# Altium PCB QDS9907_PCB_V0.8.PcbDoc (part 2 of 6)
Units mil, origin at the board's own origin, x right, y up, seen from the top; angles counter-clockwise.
Board outline 3410.03 x 4010.03 mil, 8 copper layers (Top Layer, GND1, INT1, INT2, PWR1, GND2, GND3, Bottom Layer), stack 81.668 mil thick; 250 components, 129 nets, 7010 pads, 701 vias.
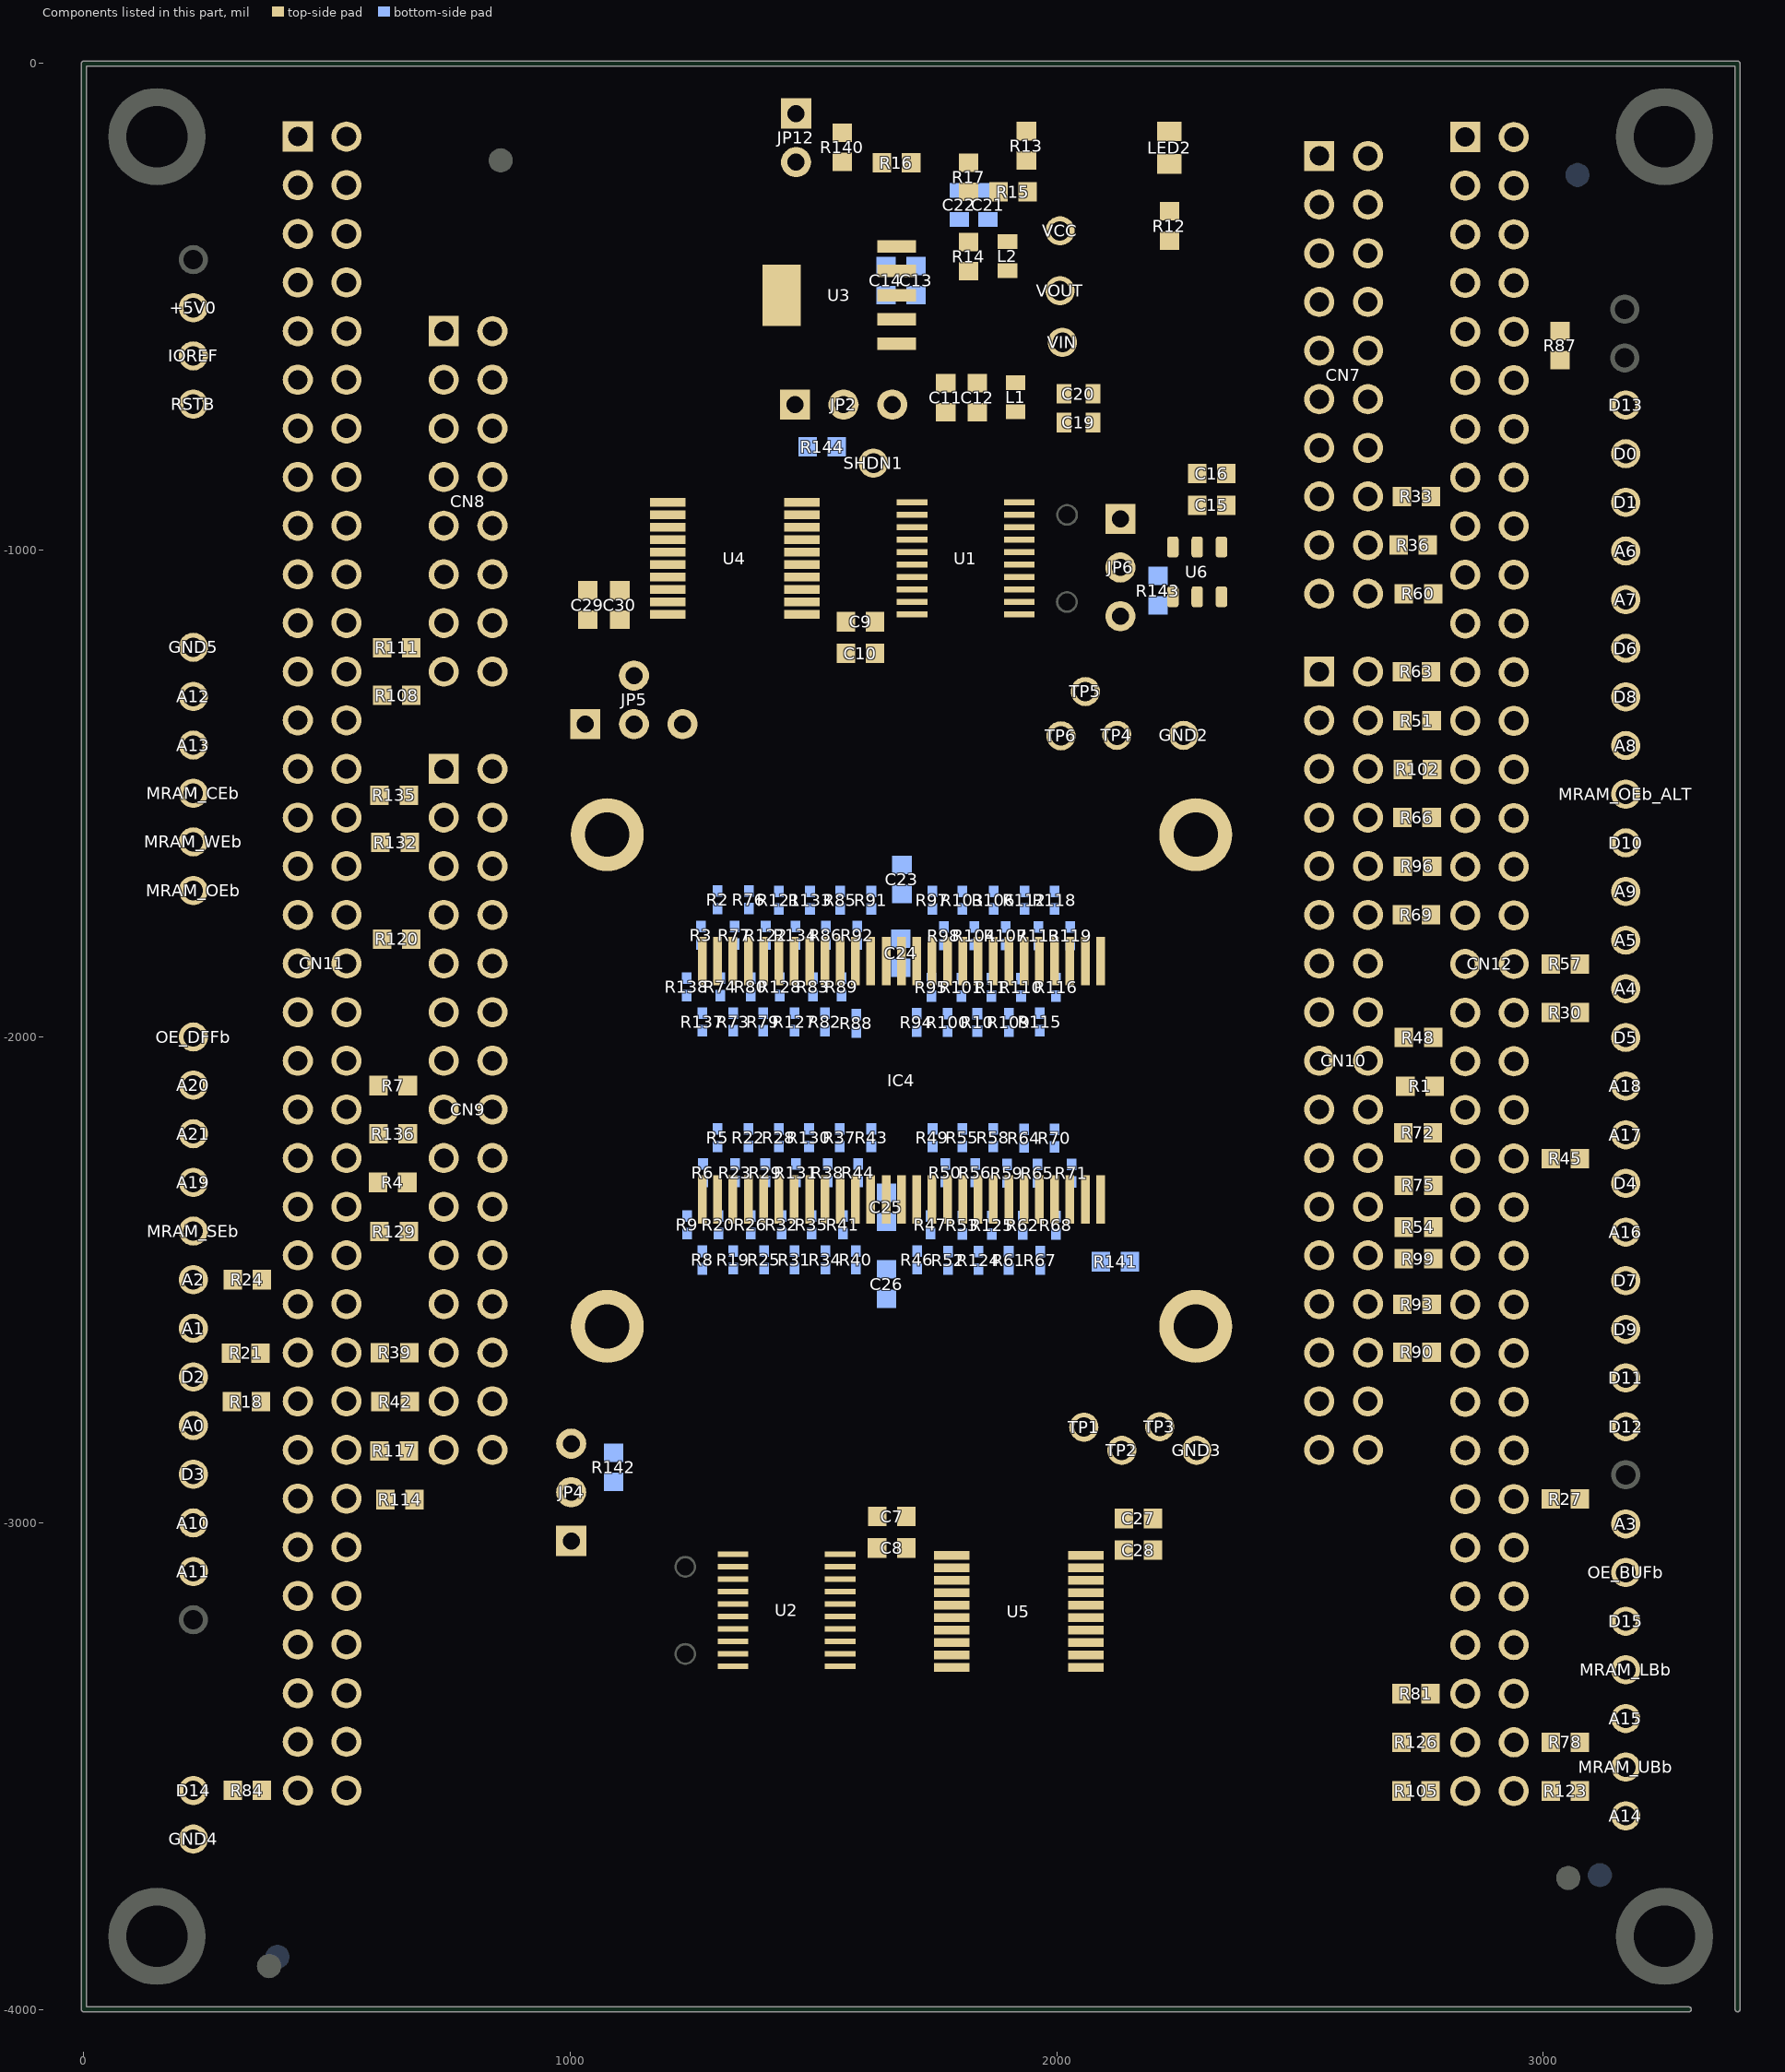
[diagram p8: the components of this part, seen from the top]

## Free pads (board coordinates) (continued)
  round 1.54 on Bottom Overlay: ""(1221.17,-3795.06) ""(1221.17,-3795.06) ""(1221.18,-3795.06) ""(1221.18,-3795.06) ""(1227.69,-3795.06) ""(1227.69,-3795.06) ""(1227.69,-3795.06) ""(1227.69,-3795.06) ""(1232.45,-3795.26) ""(1232.45,-3795.26) ""(1232.45,-3795.26) ""(1232.45,-3795.26) ""(1232.64,-3780.92) ""(1232.64,-3780.92) ""(1232.64,-3780.92) ""(1232.64,-3780.92) ""(1232.98,-3782.61) ""(1232.98,-3782.61) ""(1232.98,-3782.61) ""(1232.98,-3782.61) ""(1233.15,-3796.22) ""(1233.15,-3796.22) ""(1233.15,-3796.22) ""(1233.15,-3796.22) ""(1233.16,-3794.6) ""(1233.16,-3794.6) ""(1233.16,-3794.6) ""(1233.16,-3794.6) ""(1233.16,-3779.39) ""(1233.16,-3779.39) ""(1233.16,-3779.39) ""(1233.16,-3779.39) ""(1233.55,-3783.18) ""(1233.55,-3783.18) ""(1233.55,-3783.18) ""(1233.55,-3783.18) ""(1234.71,-3795.82) ""(1234.71,-3795.82) ""(1234.71,-3795.82) ""(1234.71,-3795.82) ""(1234.75,-3797.54) ""(1234.75,-3797.54) ""(1234.75,-3797.54) ""(1234.75,-3797.54) ""(1234.81,-3783.68) ""(1234.81,-3783.68) ""(1234.81,-3783.68) ""(1234.81,-3783.68) ""(1236.07,-3783.52) ""(1236.07,-3783.52) ""(1236.07,-3783.52) ""(1236.07,-3783.52) ""(1236.72,-3796.88) ""(1236.72,-3796.88) ""(1236.72,-3796.88) ""(1236.72,-3796.88) ""(1236.78,-3777.08) ""(1236.78,-3777.08) ""(1236.78,-3777.08) ""(1236.78,-3777.08) ""(1236.88,-3779.98) ""(1236.88,-3779.98) ""(1236.88,-3779.98) ""(1236.88,-3779.98) ""(1236.99,-3783.06) ""(1236.99,-3783.06) ""(1236.99,-3783.06) ""(1236.99,-3783.06) ""(1237.06,-3778.57) ""(1237.06,-3778.57) ""(1237.06,-3778.57) ""(1237.06,-3778.57) ""(1237.25,-3798.21) ""(1237.25,-3798.21) ""(1237.25,-3798.21) ""(1237.25,-3798.21) ""(1237.36,-3780.81) ""(1237.36,-3780.81) ""(1237.36,-3780.81) ""(1237.36,-3780.81) ""(1237.52,-3781.92) ""(1237.52,-3781.92) ""(1237.52,-3781.92) ""(1237.52,-3781.92) ""(1238.11,-3777.69) ""(1238.11,-3777.69) ""(1238.11,-3777.69) ""(1238.11,-3777.69) ""(1238.7,-3797) ""(1238.7,-3797) ""(1238.7,-3797) ""(1238.7,-3797) ""(1239.84,-3798.21) ""(1239.84,-3798.21) ""(1239.84,-3798.21) ""(1239.84,-3798.21) ""(1239.89,-3777.55) ""(1239.89,-3777.55) ""(1239.89,-3777.55) ""(1239.89,-3777.55) ""(1240.72,-3776.78) ""(1240.72,-3776.78) ""(1240.72,-3776.78) ""(1240.72,-3776.78) ""(1241.14,-3796.39) ""(1241.14,-3796.39) ""(1241.14,-3796.39) ""(1241.14,-3796.39) ""(1241.47,-3778.08) ""(1241.47,-3778.08) ""(1241.47,-3778.08) ""(1241.47,-3778.08) ""(1242.82,-3779.31) ""(1242.82,-3779.31) ""(1242.82,-3779.31) ""(1242.82,-3779.31) ""(1243.18,-3794.36) ""(1243.18,-3794.36) ""(1243.18,-3794.36) ""(1243.18,-3794.36) ""(1243.22,-3797.7) ""(1243.22,-3797.7) ""(1243.22,-3797.7) ""(1243.22,-3797.7) ""(1244.11,-3777.28) ""(1244.11,-3777.28) ""(1244.11,-3777.28) ""(1244.11,-3777.28) ""(1244.21,-3781.39) ""(1244.21,-3781.39) ""(1244.21,-3781.39) ""(1244.21,-3781.39) ""(1244.56,-3791.73) ""(1244.56,-3791.73) ""(1244.56,-3791.73) ""(1244.56,-3791.73) ""(1245.34,-3788.05) ""(1245.34,-3788.05) ""(1245.34,-3788.05) ""(1245.34,-3788.05) ""(1245.34,-3784.99) ""(1245.34,-3784.99) ""(1245.34,-3784.99) ""(1245.34,-3784.99) ""(1245.98,-3796.81) ""(1245.98,-3796.81) ""(1245.98,-3796.81) ""(1245.98,-3796.81) ""(1247.75,-3795.24) ""(1247.75,-3795.24) ""(1247.75,-3795.24) ""(1247.75,-3795.24) ""(1247.8,-3779.17) ""(1247.8,-3779.17) ""(1247.8,-3779.17) ""(1247.8,-3779.17) ""(1249.44,-3793.55) ""(1249.44,-3793.55) ""(1249.44,-3793.55) ""(1249.44,-3793.55) ""(1249.68,-3781.24) ""(1249.68,-3781.24) ""(1249.68,-3781.24) ""(1249.68,-3781.24) ""(1249.8,-3781.42) ""(1249.8,-3781.42) ""(1249.8,-3781.42) ""(1249.8,-3781.42) ""(1250.8,-3790.83) ""(1250.8,-3790.83) ""(1250.8,-3790.83) ""(1250.8,-3790.83) ""(1251.1,-3787.16) ""(1251.1,-3787.16) ""(1251.1,-3787.16) ""(1251.1,-3787.16) ""(1254.68,-3797.58) ""(1254.68,-3797.58) ""(1254.68,-3797.2) ""(1254.68,-3797.2) ""(1254.68,-3797.58) ""(1254.68,-3797.58) ""(1254.68,-3797.2) ""(1254.68,-3797.2) ""(1257.11,-3794.87) ""(1257.11,-3794.87) ""(1257.11,-3783.18) ""(1257.11,-3783.18) ""(1257.7,-3780.24) ""(1257.7,-3780.24) ""(1257.7,-3780.24) ""(1257.7,-3780.24) ""(1258.99,-3778.4) ""(1258.99,-3778.4) ""(1258.99,-3778.4) ""(1258.99,-3778.4) ""(1260.73,-3777.49) ""(1260.73,-3777.49) ""(1260.73,-3777.49) ""(1260.73,-3777.49) ""(1262.99,-3794.43) ""(1262.99,-3794.43) ""(1262.99,-3781.34) ""(1262.99,-3781.34) ""(1262.99,-3794.43) ""(1262.99,-3794.43) ""(1262.99,-3781.34) ""(1262.99,-3781.34) ""(1263.92,-3779.35) ""(1263.92,-3779.35) ""(1263.92,-3779.35) ""(1263.92,-3779.35) ""(1263.92,-3776.89) ""(1263.92,-3776.89) ""(1263.92,-3776.89) ""(1263.92,-3776.89) ""(1265.11,-3797.58) ""(1265.11,-3797.58) ""(1265.11,-3797.58) ""(1265.11,-3797.58) ""(1265.11,-3796.68) ""(1265.11,-3796.68) ""(1265.11,-3796.68) ""(1265.11,-3796.68) ""(1266,-3778.38) ""(1266,-3778.38) ""(1266,-3778.38) ""(1266,-3778.38) ""(1266.32,-3776.98) ""(1266.32,-3776.98) ""(1266.32,-3776.98) ""(1266.32,-3776.98) ""(1267.9,-3778.76) ""(1267.9,-3778.76) ""(1267.9,-3778.76) ""(1267.9,-3778.76) ""(1267.92,-3797.58) ""(1267.92,-3797.58) ""(1267.92,-3797.58) ""(1267.92,-3797.58) ""(1267.92,-3796.73) ""(1267.92,-3796.73) ""(1267.92,-3796.73) ""(1267.92,-3796.73) ""(1268.22,-3777.93) ""(1268.22,-3777.93) ""(1268.22,-3777.93) ""(1268.22,-3777.93) ""(1269.51,-3779.38) ""(1269.51,-3779.38) ""(1270.57,-3794.4) ""(1270.57,-3794.4) ""(1270.57,-3794.4) ""(1270.57,-3794.4) ""(1270.57,-3780.59) ""(1270.57,-3780.59) ""(1270.57,-3780.59) ""(1270.57,-3780.59) ""(1271.1,-3780.28) ""(1271.1,-3780.28) ""(1271.1,-3780.28) ""(1271.1,-3780.28) ""(1271.1,-3777.1) ""(1271.1,-3777.1) ""(1271.1,-3777.1) ""(1271.1,-3777.1) ""(1276.45,-3794.58) ""(1276.45,-3794.58) ""(1276.45,-3794.58) ""(1276.45,-3794.58) ""(1276.45,-3780.65) ""(1276.45,-3780.65) ""(1276.45,-3780.65) ""(1276.45,-3780.65) ""(1278.89,-3797.58) ""(1278.89,-3797.58) ""(1278.89,-3797.58) ""(1278.89,-3797.58) ""(1278.89,-3796.6) ""(1278.89,-3796.6) ""(1278.89,-3796.6) ""(1278.89,-3796.6) ""(1278.89,-3778.42) ""(1278.89,-3778.42) ""(1278.89,-3778.42) ""(1278.89,-3778.42) ""(1278.89,-3777.1) ""(1278.89,-3777.1) ""(1278.89,-3777.1) ""(1278.89,-3777.1) ""(1282.44,-3797.58) ""(1282.44,-3797.58) ""(1282.44,-3797) ""(1282.44,-3797) ""(1282.44,-3797.58) ""(1282.44,-3797.58) ""(1282.44,-3797) ""(1282.44,-3797) ""(1282.65,-3768.88) ""(1282.65,-3768.88) ""(1282.65,-3767.99) ""(1282.65,-3767.99) ""(1282.65,-3768.88) ""(1282.65,-3768.88) ""(1282.65,-3767.99) ""(1282.65,-3767.99) ""(1291.39,-3795.46) ""(1291.39,-3795.46) ""(1291.39,-3795.46) ""(1291.39,-3795.46) ""(1291.39,-3770.67) ""(1291.39,-3770.67) ""(1291.39,-3770.67) ""(1291.39,-3770.67) ""(1293.83,-3797.58) ""(1293.83,-3797.58) ""(1293.83,-3797.26) ""(1293.83,-3797.26) ""(1293.83,-3768.66) ""(1293.83,-3768.66) ""(1293.83,-3767.99) ""(1293.83,-3767.99) ""(1293.83,-3797.58) ""(1293.83,-3797.58) ""(1293.83,-3797.26) ""(1293.83,-3797.26) ""(1293.83,-3768.66) ""(1293.83,-3768.66) ""(1293.83,-3767.99) ""(1293.83,-3767.99) ""(1301.64,-3796.32) ""(1301.64,-3796.32) ""(1301.64,-3796.32) ""(1301.64,-3796.32) ""(1301.73,-3797.85) ""(1301.73,-3797.85) ""(1301.73,-3797.85) ""(1301.73,-3797.85) ""(1301.98,-3794.52) ""(1301.98,-3794.52) ""(1301.98,-3794.52) ""(1301.98,-3794.52) ""(1302.38,-3800.14) ""(1302.38,-3800.14) ""(1302.38,-3800.14) ""(1302.38,-3800.14) ""(1302.54,-3793.21) ""(1302.54,-3793.21) ""(1302.54,-3793.21) ""(1302.54,-3793.21) ""(1303.22,-3792.44) ""(1303.22,-3792.44) ""(1303.22,-3792.44) ""(1303.22,-3792.44) ""(1303.32,-3799.64) ""(1303.32,-3799.64) ""(1303.32,-3799.64) ""(1303.32,-3799.64) ""(1303.66,-3798.06) ""(1303.66,-3798.06) ""(1303.66,-3798.06) ""(1303.66,-3798.06) ""(1303.73,-3802.54) ""(1303.73,-3802.54) ""(1303.73,-3802.54) ""(1303.73,-3802.54) ""(1303.81,-3800.97) ""(1303.81,-3800.97) ""(1303.81,-3800.97) ""(1303.81,-3800.97) ""(1303.88,-3791.87) ""(1303.88,-3791.87) ""(1303.88,-3791.87) ""(1303.88,-3791.87) ""(1304.46,-3791.65) ""(1304.46,-3791.65) ""(1304.46,-3791.65) ""(1304.46,-3791.65) ""(1304.67,-3802.08) ""(1304.67,-3802.08) ""(1304.67,-3802.08) ""(1304.67,-3802.08) ""(1305.13,-3804.03) ""(1305.13,-3804.03) ""(1305.13,-3804.03) ""(1305.13,-3804.03) ""(1305.33,-3791.7) ""(1305.33,-3791.7) ""(1305.33,-3791.7) ""(1305.33,-3791.7) ""(1306.2,-3797.93) ""(1306.2,-3797.93) ""(1306.2,-3797.93) ""(1306.2,-3797.93) ""(1306.28,-3791.7) ""(1306.28,-3791.7) ""(1306.28,-3791.7) ""(1306.28,-3791.7) ""(1306.28,-3803.57) ""(1306.28,-3803.57) ""(1306.28,-3803.57) ""(1306.28,-3803.57) ""(1306.57,-3805.17) ""(1306.57,-3805.17) ""(1306.57,-3805.17) ""(1306.57,-3805.17) ""(1306.83,-3797.56) ""(1306.83,-3797.56) ""(1306.83,-3797.56) ""(1306.83,-3797.56) ""(1306.9,-3792.03) ""(1306.9,-3792.03) ""(1306.9,-3792.03) ""(1306.9,-3792.03) ""(1307.31,-3804.44) ""(1307.31,-3804.44) ""(1307.31,-3804.44) ""(1307.31,-3804.44) ""(1307.44,-3797.05) ""(1307.44,-3797.05) ""(1307.44,-3797.05) ""(1307.44,-3797.05) ""(1307.52,-3792.38) ""(1307.52,-3792.38) ""(1307.52,-3792.38) ""(1307.52,-3792.38) ""(1307.92,-3796.52) ""(1307.92,-3796.52) ""(1307.92,-3796.52) ""(1307.92,-3796.52) ""(1307.94,-3792.87) ""(1307.94,-3792.87) ""(1307.94,-3792.87) ""(1307.94,-3792.87) ""(1308.17,-3795.71) ""(1308.17,-3795.71) ""(1308.17,-3795.71) ""(1308.17,-3795.71) ""(1308.17,-3793.48) ""(1308.17,-3793.48) ""(1308.17,-3793.48) ""(1308.17,-3793.48) ""(1308.21,-3794.66) ""(1308.21,-3794.66) ""(1308.21,-3794.66) ""(1308.21,-3794.66) ""(1314.53,-3790.1) ""(1314.53,-3790.1) ""(1314.53,-3790.1) ""(1314.53,-3790.1) ""(1314.6,-3791.61) ""(1314.6,-3791.61) ""(1314.6,-3791.61) ""(1314.6,-3791.61) ""(1314.8,-3788.8) ""(1314.8,-3788.8) ""(1314.8,-3788.8) ""(1314.8,-3788.8) ""(1315.22,-3787.7) ""(1315.22,-3787.7) ""(1315.22,-3787.7) ""(1315.22,-3787.7) ""(1315.29,-3793.46) ""(1315.29,-3793.46) ""(1315.29,-3793.46) ""(1315.29,-3793.46) ""(1315.29,-3781.37) ""(1315.29,-3781.37) ""(1315.29,-3781.37) ""(1315.29,-3781.37) ""(1315.29,-3780.27) ""(1315.29,-3780.27) ""(1315.29,-3780.27) ""(1315.29,-3780.27) ""(1315.49,-3779.24) ""(1315.49,-3779.24) ""(1315.56,-3781.92) ""(1315.56,-3781.92) ""(1315.56,-3781.92) ""(1315.56,-3781.92) ""(1315.63,-3786.95) ""(1315.63,-3786.95) ""(1315.63,-3786.95) ""(1315.63,-3786.95) ""(1315.97,-3782.47) ""(1315.97,-3782.47) ""(1315.97,-3782.47) ""(1315.97,-3782.47) ""(1316.04,-3794.63) ""(1316.04,-3794.63) ""(1316.04,-3794.63) ""(1316.04,-3794.63) ""(1316.11,-3778.42) ""(1316.11,-3778.42) ""(1316.11,-3778.42) ""(1316.11,-3778.42) ""(1316.59,-3786.12) ""(1316.59,-3786.12) ""(1316.59,-3786.12) ""(1316.59,-3786.12) ""(1316.93,-3783.02) ""(1316.93,-3783.02) ""(1317,-3777.67) ""(1317,-3777.67) ""(1317.07,-3795.59) ""(1317.07,-3795.59) ""(1317.07,-3795.59) ""(1317.07,-3795.59) ""(1317.83,-3783.36) ""(1317.83,-3783.36) ""(1317.83,-3783.36) ""(1317.83,-3783.36) ""(1318.31,-3776.91) ""(1318.31,-3776.91) ""(1318.31,-3776.91) ""(1318.31,-3776.91) ""(1318.38,-3785.3) ""(1318.38,-3785.3) ""(1318.38,-3785.3) ""(1318.38,-3785.3) ""(1318.72,-3796.62) ""(1318.72,-3796.62) ""(1318.72,-3796.62) ""(1318.72,-3796.62) ""(1319.13,-3776.64) ""(1319.13,-3776.64) ""(1319.13,-3776.64) ""(1319.13,-3776.64) ""(1320.03,-3797.31) ""(1320.03,-3797.31) ""(1320.03,-3797.31) ""(1320.03,-3797.31) ""(1320.23,-3784.54) ""(1320.23,-3784.54) ""(1320.23,-3784.54) ""(1320.23,-3784.54) ""(1320.3,-3792.97) ""(1320.3,-3792.97) ""(1320.3,-3792.97) ""(1320.3,-3792.97) ""(1320.3,-3783.17) ""(1320.3,-3783.17) ""(1320.3,-3783.17) ""(1320.3,-3783.17) ""(1320.44,-3793.66) ""(1320.44,-3793.66) ""(1320.44,-3792.15) ""(1320.44,-3792.15) ""(1320.44,-3793.66) ""(1320.44,-3793.66) ""(1320.44,-3792.15) ""(1320.44,-3792.15) ""(1320.64,-3794.14) ""(1320.64,-3794.14) ""(1320.64,-3794.14) ""(1320.64,-3794.14) ""(1320.71,-3791.6) ""(1320.71,-3791.6) ""(1320.71,-3791.6) ""(1320.71,-3791.6) ""(1320.71,-3776.36) ""(1320.71,-3776.36) ""(1320.71,-3776.36) ""(1320.71,-3776.36) ""(1320.85,-3782.69) ""(1320.85,-3782.69) ""(1320.85,-3782.69) ""(1320.85,-3782.69) ""(1320.85,-3780.49) ""(1320.85,-3780.49) ""(1320.85,-3780.49) ""(1320.85,-3780.49) ""(1320.85,-3780.29) ""(1320.85,-3780.29) ""(1320.85,-3780.29) ""(1320.85,-3780.29) ""(1320.99,-3780.97) ""(1320.99,-3780.97) ""(1320.99,-3780.97) ""(1320.99,-3780.97) ""(1320.99,-3779.87) ""(1320.99,-3779.87) ""(1320.99,-3779.87) ""(1320.99,-3779.87) ""(1321.06,-3782.14) ""(1321.06,-3782.14) ""(1321.06,-3782.14) ""(1321.06,-3782.14) ""(1321.12,-3781.45) ""(1321.12,-3781.45) ""(1321.12,-3781.45) ""(1321.12,-3781.45) ""(1321.12,-3779.81) ""(1321.12,-3779.81) ""(1321.12,-3779.81) ""(1321.12,-3779.81) ""(1321.26,-3794.62) ""(1321.26,-3794.62) ""(1321.26,-3794.62) ""(1321.26,-3794.62) ""(1321.4,-3791.12) ""(1321.4,-3791.12) ""(1321.4,-3791.12) ""(1321.4,-3791.12) ""(1321.47,-3779.46) ""(1321.47,-3779.46) ""(1321.47,-3779.46) ""(1321.47,-3779.46) ""(1321.67,-3784.06) ""(1321.67,-3784.06) ""(1321.67,-3784.06) ""(1321.67,-3784.06) ""(1321.88,-3794.96) ""(1321.88,-3794.96) ""(1321.88,-3794.96) ""(1321.88,-3794.96) ""(1322.22,-3790.71) ""(1322.22,-3790.71) ""(1322.22,-3779.26) ""(1322.22,-3779.26) ""(1322.5,-3776.43) ""(1322.5,-3776.43) ""(1322.5,-3776.43) ""(1322.5,-3776.43) ""(1323.12,-3779.19) ""(1323.12,-3779.19) ""(1323.12,-3779.19) ""(1323.12,-3779.19) ""(1323.19,-3783.51) ""(1323.19,-3783.51) ""(1323.19,-3783.51) ""(1323.19,-3783.51) ""(1323.25,-3795.37) ""(1323.25,-3795.37) ""(1323.25,-3795.37) ""(1323.25,-3795.37) ""(1323.94,-3797.79) ""(1323.94,-3797.79) ""(1323.94,-3797.79) ""(1323.94,-3797.79) ""(1324.01,-3779.19) ""(1324.01,-3779.19) ""(1324.01,-3779.19) ""(1324.01,-3779.19) ""(1324.15,-3776.64) ""(1324.15,-3776.64) ""(1324.15,-3776.64) ""(1324.15,-3776.64) ""(1324.35,-3795.51) ""(1324.35,-3795.51) ""(1324.35,-3783.03) ""(1324.35,-3783.03) ""(1324.83,-3779.6) ""(1324.83,-3779.6) ""(1324.83,-3779.6) ""(1324.83,-3779.6) ""(1325.04,-3782.76) ""(1325.04,-3782.76) ""(1325.04,-3782.76) ""(1325.04,-3782.76) ""(1325.25,-3780.08) ""(1325.25,-3780.08) ""(1325.25,-3780.08) ""(1325.25,-3780.08) ""(1325.38,-3782.28) ""(1325.38,-3782.28) ""(1325.38,-3782.28) ""(1325.38,-3782.28) ""(1325.45,-3795.44) ""(1325.45,-3795.44) ""(1325.45,-3795.44) ""(1325.45,-3795.44) ""(1325.52,-3781.73) ""(1325.52,-3781.73) ""(1325.52,-3781.73) ""(1325.52,-3781.73) ""(1325.52,-3781.11) ""(1325.52,-3781.11) ""(1325.52,-3781.11) ""(1325.52,-3781.11) ""(1325.8,-3792.35) ""(1325.8,-3792.35) ""(1325.8,-3792.35) ""(1325.8,-3792.35) ""(1325.87,-3793.18) ""(1325.87,-3793.18) ""(1326,-3791.6) ""(1326,-3791.6) ""(1326,-3791.6) ""(1326,-3791.6) ""(1326.07,-3793.59) ""(1326.07,-3793.59) ""(1326.07,-3793.59) ""(1326.07,-3793.59) ""(1326.07,-3777.12) ""(1326.07,-3777.12) ""(1326.07,-3777.12) ""(1326.07,-3777.12) ""(1326.21,-3797.65) ""(1326.21,-3797.65) ""(1326.21,-3797.65) ""(1326.21,-3797.65) ""(1326.28,-3795.31) ""(1326.28,-3795.31) ""(1326.28,-3793.66) ""(1326.28,-3793.66) ""(1326.28,-3795.31) ""(1326.28,-3795.31) ""(1326.28,-3793.66) ""(1326.28,-3793.66) ""(1326.69,-3794.07) ""(1326.69,-3794.07) ""(1326.69,-3794.07) ""(1326.69,-3794.07) ""(1326.76,-3794.96) ""(1326.76,-3794.96) ""(1326.76,-3794.96) ""(1326.76,-3794.96) ""(1326.83,-3794.62) ""(1326.83,-3794.62) ""(1326.83,-3794.62) ""(1326.83,-3794.62) ""(1326.96,-3790.91) ""(1326.96,-3790.91) ""(1326.96,-3790.91) ""(1326.96,-3790.91) ""(1327.58,-3777.8) ""(1327.58,-3777.8) ""(1327.58,-3777.8) ""(1327.58,-3777.8) ""(1327.79,-3790.5) ""(1327.79,-3790.5) ""(1327.79,-3790.5) ""(1327.79,-3790.5) ""(1327.92,-3797.38) ""(1327.92,-3797.38) ""(1327.93,-3797.38) ""(1327.93,-3797.38) ""(1328.2,-3788.17) ""(1328.2,-3788.17) ""(1328.2,-3788.17) ""(1328.2,-3788.17) ""(1328.61,-3790.43) ""(1328.61,-3790.43) ""(1328.61,-3790.43) ""(1328.61,-3790.43) ""(1328.82,-3778.56) ""(1328.82,-3778.56) ""(1328.82,-3778.56) ""(1328.82,-3778.56) ""(1329.09,-3797.03) ""(1329.09,-3797.03) ""(1329.09,-3797.03) ""(1329.09,-3797.03) ""(1329.37,-3787.34) ""(1329.37,-3787.34) ""(1329.37,-3787.34) ""(1329.37,-3787.34) ""(1329.71,-3779.45) ""(1329.71,-3779.45) ""(1329.71,-3779.45) ""(1329.71,-3779.45) ""(1329.99,-3790.57) ""(1329.99,-3790.57) ""(1329.99,-3790.57) ""(1329.99,-3790.57) ""(1330.26,-3786.52) ""(1330.26,-3786.52) ""(1330.26,-3786.52) ""(1330.26,-3786.52) ""(1330.33,-3796.28) ""(1330.33,-3796.28) ""(1330.33,-3796.28) ""(1330.33,-3796.28) ""(1330.33,-3780.34) ""(1330.33,-3780.34) ""(1330.33,-3780.34) ""(1330.33,-3780.34) ""(1330.6,-3790.98) ""(1330.6,-3790.98) ""(1330.6,-3790.98) ""(1330.6,-3790.98) ""(1330.88,-3795.65) ""(1330.88,-3795.65) ""(1330.88,-3785.56) ""(1330.88,-3785.56) ""(1330.88,-3781.17) ""(1330.88,-3781.17) ""(1330.88,-3795.65) ""(1330.88,-3795.65) ""(1330.88,-3785.56) ""(1330.88,-3785.56) ""(1330.88,-3781.17) ""(1330.88,-3781.17) ""(1331.15,-3781.99) ""(1331.15,-3781.99) ""(1331.15,-3781.99) ""(1331.15,-3781.99) ""(1331.22,-3784.46) ""(1331.22,-3784.46) ""(1331.22,-3784.46) ""(1331.22,-3784.46) ""(1331.29,-3783.09) ""(1331.29,-3783.09) ""(1331.29,-3783.09) ""(1331.29,-3783.09) ""(1331.36,-3794.82) ""(1331.36,-3794.82) ""(1331.36,-3794.82) ""(1331.36,-3794.82) ""(1331.36,-3791.6) ""(1331.36,-3791.6) ""(1331.36,-3791.6) ""(1331.36,-3791.6) ""(1331.64,-3792.28) ""(1331.64,-3792.28) ""(1331.64,-3792.28) ""(1331.64,-3792.28) ""(1331.7,-3793.93) ""(1331.7,-3793.93) ""(1331.7,-3793.93) ""(1331.7,-3793.93) ""(1331.77,-3793.04) ""(1331.77,-3793.04) ""(1331.77,-3793.04) ""(1331.77,-3793.04) ""(1334.7,-3786.63) ""(1334.7,-3785.75) ""(1334.7,-3785.75) ""(1334.7,-3786.63) ""(1334.7,-3786.63) ""(1334.7,-3786.63) ""(1334.7,-3785.75) ""(1334.7,-3785.75) ""(1334.7,-3786.63) ""(1334.91,-3784.17) ""(1334.91,-3784.17) ""(1334.91,-3784.17) ""(1334.91,-3784.17) ""(1334.98,-3794.4) ""(1334.98,-3794.4) ""(1334.98,-3794.4) ""(1334.98,-3794.4) ""(1334.98,-3794.4) ""(1335.06,-3793.31) ""(1335.06,-3793.31) ""(1335.06,-3793.31) ""(1335.06,-3793.31) ""(1335.06,-3793.31) ""(1335.11,-3783.01) ""(1335.11,-3783.01) ""(1335.11,-3783.01) ""(1335.11,-3783.01) ""(1335.47,-3787.4) ""(1335.47,-3787.4) ""(1335.47,-3787.4) ""(1335.47,-3787.4) ""(1335.47,-3787.4) ""(1335.86,-3792.64) ""(1335.86,-3792.64) ""(1335.86,-3792.64) ""(1335.86,-3792.64) ""(1335.86,-3792.64) ""(1335.87,-3795.43) ""(1335.87,-3795.43) ""(1335.87,-3795.43) ""(1335.87,-3795.43) ""(1335.87,-3781.36) ""(1335.87,-3781.36) ""(1335.87,-3781.36) ""(1335.87,-3781.36) ""(1336.76,-3796.32) ""(1336.76,-3796.32) ""(1336.76,-3779.92) ""(1336.76,-3779.92) ""(1336.76,-3796.32) ""(1336.76,-3796.32) ""(1336.76,-3779.92) ""(1336.76,-3779.92) ""(1336.9,-3792.68) ""(1336.9,-3792.68) ""(1336.9,-3792.68) ""(1336.9,-3792.68) ""(1336.9,-3792.68) ""(1337.45,-3793.23) ""(1337.45,-3793.23) ""(1337.79,-3778.89) ""(1337.79,-3778.89) ""(1337.79,-3778.89) ""(1337.79,-3778.89) ""(1338.34,-3797.28) ""(1338.34,-3797.28) ""(1338.34,-3797.28) ""(1338.34,-3797.28) ""(1338.55,-3794.06) ""(1338.55,-3794.06) ""(1338.55,-3794.06) ""(1338.55,-3794.06) ""(1339.1,-3777.86) ""(1339.1,-3777.86) ""(1339.1,-3777.86) ""(1339.1,-3777.86) ""(1339.44,-3797.76) ""(1339.44,-3797.76) ""(1339.44,-3797.76) ""(1339.44,-3797.76) ""(1339.51,-3794.67) ""(1339.51,-3794.67) ""(1339.51,-3794.67) ""(1339.51,-3794.67) ""(1340.26,-3777.1) ""(1340.26,-3777.1) ""(1340.26,-3777.1) ""(1340.26,-3777.1) ""(1340.68,-3795.15) ""(1340.68,-3795.15) ""(1340.68,-3795.15) ""(1340.68,-3795.15) ""(1341.16,-3784.29) ""(1341.16,-3783.69) ""(1341.16,-3783.69) ""(1341.16,-3784.29) ""(1341.16,-3784.29) ""(1341.16,-3784.29) ""(1341.16,-3784.29) ""(1341.16,-3783.69) ""(1341.16,-3783.69) ""(1341.3,-3782.25) ""(1341.3,-3782.25) ""(1341.3,-3782.25) ""(1341.3,-3782.25) ""(1341.5,-3781.15) ""(1341.5,-3781.15) ""(1341.5,-3781.15) ""(1341.5,-3781.15) ""(1341.63,-3776.62) ""(1341.63,-3776.62) ""(1341.63,-3776.62) ""(1341.63,-3776.62) ""(1341.71,-3797.97) ""(1341.71,-3797.97) ""(1341.71,-3797.97) ""(1341.71,-3797.97) ""(1341.85,-3780.4) ""(1341.85,-3780.4) ""(1341.85,-3780.4) ""(1341.85,-3780.4) ""(1341.93,-3785.06) ""(1341.93,-3785.06) ""(1341.93,-3785.06) ""(1341.93,-3785.06) ""(1341.93,-3785.06) ""(1341.98,-3795.29) ""(1341.98,-3795.29) ""(1341.98,-3795.29) ""(1341.98,-3795.29) ""(1342.53,-3779.71) ""(1342.53,-3779.71) ""(1342.53,-3779.71) ""(1342.53,-3779.71) ""(1342.95,-3795.22) ""(1342.95,-3795.22) ""(1342.95,-3795.22) ""(1342.95,-3795.22) ""(1343.21,-3776.41) ""(1343.21,-3776.41) ""(1343.29,-3779.44) ""(1343.29,-3779.44) ""(1343.29,-3779.44) ""(1343.29,-3779.44) ""(1343.77,-3797.97) ""(1343.77,-3797.97) ""(1343.91,-3794.95) ""(1343.91,-3794.95) ""(1343.91,-3794.95) ""(1343.91,-3794.95) ""(1343.98,-3779.37) ""(1343.98,-3779.37) ""(1343.98,-3779.37) ""(1343.98,-3779.37) ""(1344.52,-3776.41) ""(1344.52,-3776.41) ""(1344.52,-3776.41) ""(1344.52,-3776.41) ""(1344.66,-3794.61) ""(1344.66,-3794.61) ""(1344.66,-3794.61) ""(1344.66,-3794.61) ""(1344.87,-3779.44) ""(1344.87,-3779.44) ""(1344.87,-3779.44) ""(1344.87,-3779.44) ""(1345.83,-3793.58) ""(1345.83,-3793.58) ""(1345.83,-3793.58) ""(1345.83,-3793.58) ""(1346.24,-3797.76) ""(1346.24,-3797.76) ""(1346.24,-3792.96) ""(1346.24,-3792.96) ""(1346.24,-3797.76) ""(1346.24,-3797.76) ""(1346.24,-3792.96) ""(1346.24,-3792.96) ""(1346.45,-3780.6) ""(1346.45,-3780.6) ""(1346.45,-3780.6) ""(1346.45,-3780.6) ""(1346.47,-3785.06) ""(1346.47,-3785.06) ""(1346.47,-3785.06) ""(1346.47,-3785.06) ""(1346.47,-3785.06) ""(1346.57,-3787.4) ""(1346.57,-3787.4) ""(1346.57,-3787.4) ""(1346.57,-3787.4) ""(1346.57,-3787.4) ""(1346.65,-3776.55) ""(1346.65,-3776.55) ""(1346.65,-3776.55) ""(1346.65,-3776.55) ""(1346.72,-3781.29) ""(1346.72,-3781.29) ""(1346.72,-3781.29) ""(1346.72,-3781.29) ""(1346.79,-3791.52) ""(1346.79,-3791.52) ""(1346.79,-3791.52) ""(1346.79,-3791.52) ""(1347,-3790.69) ""(1347,-3790.69) ""(1347,-3790.69) ""(1347,-3790.69) ""(1347.15,-3782.67) ""(1347.15,-3782.67) ""(1347.15,-3782.67) ""(1347.15,-3782.67) ""(1347.15,-3782.67) ""(1347.18,-3782.87) ""(1347.18,-3782.87) ""(1347.18,-3782.87) ""(1347.18,-3782.87) ""(1347.18,-3782.87) ""(1347.21,-3789.6) ""(1347.21,-3789.6) ""(1347.21,-3789.6) ""(1347.21,-3789.6) ""(1347.24,-3784.26) ""(1347.24,-3784.26) ""(1347.24,-3784.26) ""(1347.24,-3784.26) ""(1347.24,-3784.26) ""(1347.34,-3788.25) ""(1347.34,-3788.25) ""(1347.34,-3788.25) ""(1347.34,-3788.25) ""(1347.34,-3788.25) ""(1348.24,-3797.15) ""(1348.24,-3797.15) ""(1348.24,-3797.15) ""(1348.24,-3797.15) ""(1348.58,-3777.45) ""(1348.58,-3777.45) ""(1348.58,-3777.45) ""(1348.58,-3777.45) ""(1349.54,-3796.53) ""(1349.54,-3796.53) ""(1349.95,-3778.41) ""(1349.95,-3778.41) ""(1349.95,-3778.41) ""(1349.95,-3778.41) ""(1351.05,-3779.37) ""(1351.05,-3779.37) ""(1351.05,-3779.37) ""(1351.05,-3779.37) ""(1351.12,-3795.43) ""(1351.12,-3795.43) ""(1351.12,-3795.43) ""(1351.12,-3795.43) ""(1352.15,-3780.54) ""(1352.15,-3780.54) ""(1352.15,-3780.54) ""(1352.15,-3780.54) ""(1352.91,-3781.77) ""(1352.91,-3781.77) ""(1352.91,-3781.77) ""(1352.91,-3781.77) ""(1353.18,-3792.75) ""(1353.18,-3792.75) ""(1353.18,-3792.75) ""(1353.18,-3792.75) ""(1353.53,-3783.14) ""(1353.53,-3783.14) ""(1353.53,-3783.14) ""(1353.53,-3783.14) ""(1353.8,-3791.31) ""(1353.8,-3791.31) ""(1353.8,-3791.31) ""(1353.8,-3791.31) ""(1353.94,-3784.31) ""(1353.94,-3784.31) ""(1353.94,-3784.31) ""(1353.94,-3784.31) ""(1354.14,-3789.39) ""(1354.14,-3789.39) ""(1354.14,-3789.39) ""(1354.14,-3789.39) ""(1354.21,-3785.75) ""(1354.21,-3785.75) ""(1354.21,-3785.75) ""(1354.21,-3785.75) ""(1354.28,-3787.67) ""(1354.28,-3787.67) ""(1354.28,-3787.67) ""(1354.28,-3787.67) ""(1356.81,-3794.13) ""(1356.81,-3794.13) ""(1356.81,-3794.13) ""(1356.81,-3794.13) ""(1356.81,-3794.13) ""(1356.83,-3795.19) ""(1356.83,-3795.19) ""(1356.83,-3795.19) ""(1356.83,-3795.19) ""(1356.83,-3795.19) ""(1357.11,-3782.05) ""(1357.11,-3782.05) ""(1357.11,-3782.05) ""(1357.11,-3782.05) ""(1357.25,-3780.34) ""(1357.25,-3780.34) ""(1357.25,-3780.34) ""(1357.25,-3780.34) ""(1357.39,-3783.08) ""(1357.39,-3783.08) ""(1357.39,-3783.08) ""(1357.39,-3783.08) ""(1357.59,-3795.99) ""(1357.59,-3795.99) ""(1357.59,-3795.99) ""(1357.59,-3795.99) ""(1357.62,-3793.26) ""(1357.62,-3793.26) ""(1357.62,-3793.26) ""(1357.62,-3793.26) ""(1357.62,-3793.26) ""(1357.66,-3779.51) ""(1357.66,-3779.51) ""(1357.66,-3779.51) ""(1357.66,-3779.51) ""(1358.08,-3783.97) ""(1358.08,-3783.97) ""(1358.08,-3783.97) ""(1358.08,-3783.97) ""(1358.28,-3778.62) ""(1358.28,-3778.62) ""(1358.28,-3778.62) ""(1358.28,-3778.62) ""(1358.49,-3796.6) ""(1358.49,-3796.6) ""(1358.49,-3796.6) ""(1358.49,-3796.6) ""(1358.67,-3793.18) ""(1358.67,-3793.18) ""(1358.68,-3793.18) ""(1358.68,-3793.18) ""(1358.68,-3793.18) ""(1358.83,-3784.32) ""(1358.83,-3784.32) ""(1358.83,-3784.32) ""(1358.83,-3784.32) ""(1359.17,-3777.87) ""(1359.17,-3777.87) ""(1359.17,-3777.87) ""(1359.17,-3777.87) ""(1359.24,-3793.65) ""(1359.24,-3793.65) ""(1359.24,-3793.65) ""(1359.24,-3793.65) ""(1359.59,-3784.59) ""(1359.59,-3784.59) ""(1359.59,-3784.59) ""(1359.59,-3784.59) ""(1359.79,-3797.29) ""(1359.79,-3797.29) ""(1359.79,-3797.29) ""(1359.79,-3797.29) ""(1360,-3777.32) ""(1360,-3777.32) ""(1360,-3777.32) ""(1360,-3777.32) ""(1360.34,-3794.34) ""(1360.34,-3794.34) ""(1360.34,-3794.34) ""(1360.34,-3794.34) ""(1360.55,-3784.73) ""(1360.55,-3784.73) ""(1360.55,-3784.73) ""(1360.55,-3784.73) ""(1360.82,-3797.56) ""(1360.82,-3797.56) ""(1360.82,-3797.56) ""(1360.82,-3797.56) ""(1361.24,-3776.97) ""(1361.24,-3776.97) ""(1361.24,-3776.97) ""(1361.24,-3776.97) ""(1361.47,-3784.66) ""(1361.47,-3784.66) ""(1361.47,-3784.66) ""(1361.47,-3784.66) ""(1361.7,-3784.56) ""(1361.7,-3784.56) ""(1361.7,-3784.56) ""(1361.7,-3784.56) ""(1361.86,-3780.43) ""(1361.86,-3780.43) ""(1361.86,-3780.43) ""(1361.86,-3780.43) ""(1361.89,-3780.64) ""(1361.89,-3780.64) ""(1361.89,-3780.64) ""(1361.89,-3780.64) ""(1361.92,-3795.02) ""(1361.92,-3795.02) ""(1361.92,-3795.02) ""(1361.92,-3795.02) ""(1361.92,-3780.1) ""(1361.92,-3780.1) ""(1361.92,-3780.1) ""(1361.92,-3780.1) ""(1361.97,-3780.82) ""(1361.97,-3780.82) ""(1361.97,-3780.82) ""(1361.97,-3780.82) ""(1362.02,-3779.91) ""(1362.02,-3779.91) ""(1362.02,-3779.91) ""(1362.02,-3779.91) ""(1362.04,-3784.25) ""(1362.04,-3784.25) ""(1362.04,-3784.25) ""(1362.04,-3784.25) ""(1362.06,-3797.63) ""(1362.06,-3797.63) ""(1362.06,-3797.63) ""(1362.06,-3797.63) ""(1362.14,-3780.99) ""(1362.14,-3780.99) ""(1362.14,-3780.99) ""(1362.14,-3780.99) ""(1362.2,-3779.72) ""(1362.2,-3779.72) ""(1362.2,-3779.72) ""(1362.2,-3779.72) ""(1362.24,-3783.97) ""(1362.24,-3783.97) ""(1362.24,-3783.97) ""(1362.24,-3783.97) ""(1362.26,-3781.12) ""(1362.26,-3781.12) ""(1362.26,-3781.12) ""(1362.26,-3781.12) ""(1362.43,-3781.38) ""(1362.43,-3781.38) ""(1362.43,-3781.38) ""(1362.43,-3781.38) ""(1362.47,-3783.63) ""(1362.47,-3783.63) ""(1362.47,-3783.63) ""(1362.47,-3783.63) ""(1362.58,-3781.66) ""(1362.58,-3781.66) ""(1362.58,-3781.66) ""(1362.58,-3781.66) ""(1362.68,-3783.01) ""(1362.68,-3783.01) ""(1362.68,-3783.01) ""(1362.68,-3783.01) ""(1362.68,-3776.77) ""(1362.68,-3776.77) ""(1362.68,-3776.77) ""(1362.68,-3776.77) ""(1362.7,-3782.08) ""(1362.7,-3782.08) ""(1362.7,-3782.08) ""(1362.7,-3782.08) ""(1362.71,-3782.56) ""(1362.71,-3782.56) ""(1362.71,-3782.56) ""(1362.71,-3782.56) ""(1363.23,-3795.16) ""(1363.23,-3795.16) ""(1363.23,-3795.16) ""(1363.23,-3795.16) ""(1363.43,-3779.31) ""(1363.43,-3779.31) ""(1363.43,-3779.31) ""(1363.43,-3779.31) ""(1364.05,-3795.02) ""(1364.05,-3795.02) ""(1364.05,-3795.02) ""(1364.05,-3795.02) ""(1364.33,-3779.37) ""(1364.33,-3779.37) ""(1364.33,-3779.37) ""(1364.33,-3779.37) ""(1364.46,-3797.63) ""(1364.46,-3797.63) ""(1364.46,-3776.77) ""(1364.46,-3776.77) ""(1364.46,-3797.63) ""(1364.46,-3797.63) ""(1364.46,-3776.77) ""(1364.46,-3776.77) ""(1364.94,-3794.82) ""(1364.94,-3794.82) ""(1364.94,-3794.82) ""(1364.94,-3794.82) ""(1365.49,-3779.72) ""(1365.49,-3779.72) ""(1365.49,-3779.72) ""(1365.49,-3779.72) ""(1365.63,-3794.34) ""(1365.63,-3794.34) ""(1365.63,-3794.34) ""(1365.63,-3794.34) ""(1365.95,-3797.67) ""(1365.95,-3797.67) ""(1365.95,-3797.67) ""(1365.95,-3797.67) ""(1366.39,-3793.79) ""(1366.39,-3793.79) ""(1366.39,-3776.9) ""(1366.39,-3776.9) ""(1366.39,-3793.79) ""(1366.39,-3793.79) ""(1366.39,-3776.9) ""(1366.39,-3776.9) ""(1366.46,-3780.47) ""(1366.46,-3780.47) ""(1366.46,-3780.47) ""(1366.46,-3780.47) ""(1366.88,-3797.6) ""(1366.88,-3797.6) ""(1367.01,-3792.96) ""(1367.01,-3792.96) ""(1367.01,-3792.96) ""(1367.01,-3792.96) ""(1367.21,-3781.57) ""(1367.21,-3781.57) ""(1367.21,-3781.57) ""(1367.21,-3781.57) ""(1367.49,-3792) ""(1367.49,-3792) ""(1367.49,-3792) ""(1367.49,-3792) ""(1367.51,-3797.45) ""(1367.51,-3797.45) ""(1367.51,-3797.45) ""(1367.51,-3797.45) ""(1367.83,-3783.01) ""(1367.83,-3783.01) ""(1367.83,-3783.01) ""(1367.83,-3783.01) ""(1367.9,-3790.7) ""(1367.9,-3790.7) ""(1367.9,-3790.7) ""(1367.9,-3790.7) ""(1368.04,-3784.11) ""(1368.04,-3784.11) ""(1368.04,-3784.11) ""(1368.04,-3784.11) ""(1368.17,-3785.48) ""(1368.17,-3785.48) ""(1368.17,-3785.48) ""(1368.17,-3785.48) ""(1368.24,-3789.12) ""(1368.24,-3789.12) ""(1368.24,-3789.12) ""(1368.24,-3789.12) ""(1368.31,-3787.4) ""(1368.31,-3787.4) ""(1368.31,-3787.4) ""(1368.31,-3787.4) ""(1368.41,-3797.13) ""(1368.41,-3797.13) ""(1368.41,-3797.13) ""(1368.41,-3797.13) ""(1368.45,-3777.32) ""(1368.45,-3777.32) ""(1368.45,-3777.32) ""(1368.45,-3777.32) ""(1369.23,-3796.68) ""(1369.23,-3796.68) ""(1369.23,-3796.68) ""(1369.23,-3796.68) ""(1369.9,-3796.26) ""(1369.9,-3796.26) ""(1369.9,-3796.26) ""(1369.9,-3796.26) ""(1370.03,-3778.07) ""(1370.03,-3778.07) ""(1370.03,-3778.07) ""(1370.03,-3778.07) ""(1370.57,-3795.72) ""(1370.57,-3795.72) ""(1370.57,-3795.72) ""(1370.57,-3795.72) ""(1371.33,-3779.17) ""(1371.33,-3779.17) ""(1371.33,-3779.17) ""(1371.33,-3779.17) ""(1371.46,-3795.02) ""(1371.46,-3795.02) ""(1371.46,-3795.02) ""(1371.46,-3795.02) ""(1372.01,-3794.5) ""(1372.01,-3794.5) ""(1372.01,-3794.5) ""(1372.01,-3794.5) ""(1372.44,-3794.06) ""(1372.44,-3794.06) ""(1372.44,-3794.06) ""(1372.44,-3794.06) ""(1372.84,-3780.47) ""(1372.84,-3780.47) ""(1372.84,-3780.47) ""(1372.84,-3780.47) ""(1372.98,-3793.38) ""(1372.98,-3793.38) ""(1372.98,-3793.38) ""(1372.98,-3793.38) ""(1373.74,-3781.85) ""(1373.74,-3781.85) ""(1373.74,-3781.85) ""(1373.74,-3781.85) ""(1373.94,-3791.59) ""(1373.94,-3791.59) ""(1373.94,-3791.59) ""(1373.94,-3791.59) ""(1374.42,-3783.49) ""(1374.42,-3783.49) ""(1374.43,-3783.49) ""(1374.43,-3783.49) ""(1374.63,-3789.74) ""(1374.63,-3789.74) ""(1374.63,-3789.74) ""(1374.63,-3789.74) ""(1374.77,-3785) ""(1374.77,-3785) ""(1374.77,-3785) ""(1374.77,-3785) ""(1374.84,-3787.95) ""(1374.84,-3787.95) ""(1374.84,-3787.95) ""(1374.84,-3787.95) ""(1374.97,-3786.65) ""(1374.97,-3786.65) ""(1374.97,-3786.65) ""(1374.97,-3786.65) ""(1376.92,-3796.59) ""(1376.92,-3796.59) ""(1376.92,-3796.59) ""(1376.92,-3796.59) ""(1376.92,-3796.59) ""(1376.92,-3795.66) ""(1376.92,-3795.66) ""(1376.92,-3795.66) ""(1376.92,-3795.66) ""(1376.92,-3795.66) ""(1378.49,-3794.89) ""(1378.49,-3794.89) ""(1378.49,-3794.89) ""(1378.49,-3794.89) ""(1378.49,-3794.89) ""(1379.12,-3770.02) ""(1379.26,-3794.12) ""(1379.26,-3794.12) ""(1379.26,-3794.12) ""(1379.26,-3794.12) ""(1379.26,-3794.12) ""(1379.26,-3777.8) ""(1379.26,-3777.8) ""(1379.26,-3777.8) ""(1379.26,-3777.8) ""(1379.26,-3777.8) ""(1380.03,-3777.03) ""(1380.03,-3777.03) ""(1380.03,-3777.03) ""(1380.03,-3777.03) ""(1380.03,-3777.03) ""(1385.3,-3794.12) ""(1385.3,-3794.12) ""(1385.3,-3780.76) ""(1385.3,-3780.76) ""(1385.3,-3794.12) ""(1385.3,-3794.12) ""(1385.3,-3794.12) ""(1385.3,-3780.76) ""(1385.3,-3780.76) ""(1385.3,-3780.76) ""(1386.07,-3794.89) ""(1386.07,-3794.89) ""(1386.07,-3794.89) ""(1386.07,-3794.89) ""(1386.07,-3794.89) ""(1386.07,-3779.99) ""(1386.07,-3779.99) ""(1386.07,-3779.99) ""(1386.07,-3779.99) ""(1386.07,-3779.99) ""(1386.4,-3770.02) ""(1387.07,-3797.36) ""(1387.07,-3797.36) ""(1387.07,-3794.89) ""(1387.07,-3794.89) ""(1387.07,-3779.99) ""(1387.07,-3779.99) ""(1387.07,-3777.03) ""(1387.07,-3777.03) ""(1387.84,-3796.59) ""(1387.84,-3796.59) ""(1387.84,-3796.59) ""(1387.84,-3796.59) ""(1387.84,-3796.59) ""(1387.84,-3795.66) ""(1387.84,-3795.66) ""(1387.84,-3795.66) ""(1387.84,-3795.66) ""(1387.84,-3795.66) ""(1387.84,-3779.22) ""(1387.84,-3779.22) ""(1387.84,-3779.22) ""(1387.84,-3779.22) ""(1387.84,-3779.22) ""(1387.84,-3777.8) ""(1387.84,-3777.8) ""(1387.84,-3777.8) ""(1387.84,-3777.8) ""(1387.84,-3777.8) ""(1391.91,-3779.29) ""(1391.91,-3779.29) ""(1391.91,-3777.8) ""(1391.91,-3777.8) ""(1391.91,-3779.29) ""(1391.91,-3779.29) ""(1391.91,-3779.29) ""(1391.91,-3777.8) ""(1391.91,-3777.8) ""(1391.91,-3777.8) ""(1392.91,-3780.06) ""(1392.91,-3780.06) ""(1392.91,-3780.06) ""(1392.91,-3780.06) ""(1392.91,-3780.06) ""(1393.61,-3780.52) ""(1393.61,-3780.52) ""(1393.61,-3780.52) ""(1393.61,-3780.52) ""(1393.61,-3780.52) ""(1396.57,-3781.15) ""(1396.57,-3781.15) ""(1396.57,-3781.15) ""(1396.57,-3781.15) ""(1396.57,-3781.15) ""(1397.28,-3780.06) ""(1397.28,-3780.06) ""(1397.28,-3780.06) ""(1397.28,-3780.06) ""(1397.28,-3780.06) ""(1398.28,-3780.06) ""(1398.28,-3780.06) ""(1398.28,-3780.06) ""(1398.28,-3780.06) ""(1398.28,-3780.06) ""(1398.28,-3777.03) ""(1398.28,-3777.03) ""(1398.28,-3777.03) ""(1398.28,-3777.03) ""(1398.28,-3777.03) ""(1399.05,-3779.29) ""(1399.05,-3779.29) ""(1399.05,-3777.8) ""(1399.05,-3777.8) ""(1399.05,-3779.29) ""(1399.05,-3779.29) ""(1399.05,-3779.29) ""(1399.05,-3777.8) ""(1399.05,-3777.8) ""(1399.05,-3777.8) ""(1400.04,-3788.78) ""(1400.04,-3788.78) ""(1400.04,-3788.77) ""(1400.04,-3788.77) ""(1400.04,-3788.77) ""(1401.05,-3796.91) ""(1401.05,-3796.91) ""(1401.05,-3796.91) ""(1401.05,-3796.91) ""(1401.05,-3796.91) ""(1401.44,-3788.78) ""(1401.44,-3788.78) ""(1401.44,-3788.77) ""(1401.44,-3788.77) ""(1401.44,-3788.77) ""(1401.75,-3797.36) ""(1401.75,-3797.36) ""(1401.75,-3797.36) ""(1401.75,-3797.36) ""(1401.75,-3797.36) ""(1402.69,-3779.29) ""(1402.69,-3779.29) ""(1402.69,-3777.8) ""(1402.69,-3777.8) ""(1402.7,-3779.29) ""(1402.7,-3779.29) ""(1402.7,-3779.29) ""(1402.7,-3777.8) ""(1402.7,-3777.8) ""(1402.7,-3777.8) ""(1403.47,-3780.06) ""(1403.47,-3780.06) ""(1403.47,-3780.06) ""(1403.47,-3780.06) ""(1403.47,-3780.06) ""(1403.47,-3777.03) ""(1403.47,-3777.03) ""(1403.47,-3777.03) ""(1403.47,-3777.03) ""(1403.47,-3777.03) ""(1403.64,-3797.36) ""(1403.64,-3797.36) ""(1403.64,-3797.36) ""(1403.64,-3797.36) ""(1403.64,-3797.36) ""(1404.2,-3780.06) ""(1404.2,-3780.06) ""(1404.2,-3780.06) ""(1404.2,-3780.06) ""(1404.2,-3780.06) ""(1404.34,-3796.91) ""(1404.34,-3796.91) ""(1404.34,-3796.91) ""(1404.34,-3796.91) ""(1404.34,-3796.91) ""(1404.9,-3781.15) ""(1404.9,-3781.15) ""(1404.9,-3781.15) ""(1404.9,-3781.15) ""(1411.78,-3780.52) ""(1411.78,-3780.52) ""(1411.78,-3780.52) ""(1411.78,-3780.52) ""(1411.78,-3780.52) ""(1412.48,-3780.06) ""(1413.12,-3780.06) ""(1413.12,-3780.06) ""(1413.12,-3780.06) ""(1413.12,-3780.06) ""(1413.12,-3780.06) ""(1413.12,-3777.03) ""(1413.12,-3777.03) ""(1413.12,-3777.03) ""(1413.12,-3777.03) ""(1413.12,-3777.03) ""(1413.89,-3779.29) ""(1413.89,-3779.29) ""(1413.89,-3779.29) ""(1413.89,-3779.29) ""(1413.89,-3779.29) ""(1413.89,-3777.8) ""(1413.89,-3777.8) ""(1413.89,-3777.8) ""(1413.89,-3777.8) ""(1413.89,-3777.8) ""(1417.74,-3780.91) ""(1417.74,-3780.91) ""(1417.74,-3780.91) ""(1417.74,-3780.91) ""(1417.74,-3779.17) ""(1417.74,-3779.17) ""(1417.74,-3779.17) ""(1417.74,-3779.17) ""(1418,-3781.91) ""(1418,-3781.91) ""(1418,-3781.91) ""(1418,-3781.91) ""(1418.14,-3778.1) ""(1418.14,-3778.1) ""(1418.14,-3778.1) ""(1418.14,-3778.1) ""(1418.47,-3782.72) ""(1418.47,-3782.72) ""(1418.47,-3782.72) ""(1418.47,-3782.72) ""(1418.61,-3777.37) ""(1418.61,-3777.37) ""(1418.61,-3777.37) ""(1418.61,-3777.37) ""(1419.34,-3783.38) ""(1419.34,-3783.38) ""(1419.34,-3783.38) ""(1419.34,-3783.38) ""(1419.41,-3776.96) ""(1419.41,-3776.96) ""(1419.41,-3776.96) ""(1419.41,-3776.96) ""(1420.21,-3783.65) ""(1420.21,-3783.65) ""(1420.21,-3783.65) ""(1420.21,-3783.65) ""(1420.35,-3776.76) ""(1420.35,-3776.76) ""(1420.35,-3776.76) ""(1420.35,-3776.76) ""(1421.22,-3783.58) ""(1421.22,-3783.58) ""(1421.22,-3783.58) ""(1421.22,-3783.58) ""(1421.42,-3776.76) ""(1421.42,-3776.76) ""(1421.42,-3776.76) ""(1421.42,-3776.76) ""(1421.69,-3783.38) ""(1421.69,-3783.38) ""(1421.69,-3783.38) ""(1421.69,-3783.38) ""(1422.29,-3782.92) ""(1422.29,-3782.92) ""(1422.29,-3782.92) ""(1422.29,-3782.92) ""(1422.62,-3782.45) ""(1422.62,-3782.45) ""(1422.62,-3782.45) ""(1422.62,-3782.45) ""(1422.69,-3777.03) ""(1422.69,-3777.03) ""(1422.69,-3777.03) ""(1422.69,-3777.03) ""(1423.02,-3782.11) ""(1423.02,-3782.11) ""(1423.02,-3782.11) ""(1423.02,-3782.11) ""(1423.29,-3782.05) ""(1423.29,-3782.05) ""(1423.29,-3782.05) ""(1423.29,-3782.05) ""(1423.56,-3777.5) ""(1423.56,-3777.5) ""(1423.56,-3777.5) ""(1423.56,-3777.5) ""(1424.03,-3782.11) ""(1424.03,-3782.11) ""(1424.03,-3782.11) ""(1424.03,-3782.11) ""(1424.23,-3796.59) ""(1424.23,-3796.59) ""(1424.23,-3796.59) ""(1424.23,-3795.47) ""(1424.23,-3795.47) ""(1424.23,-3795.47) ""(1424.23,-3778.1) ""(1424.23,-3778.1) ""(1424.23,-3778.1) ""(1424.23,-3778.1) ""(1424.23,-3796.59) ""(1424.23,-3796.59) ""(1424.23,-3795.47) ""(1424.23,-3795.47) ""(1424.5,-3782.51) ""(1424.5,-3782.51) ""(1424.5,-3782.51) ""(1424.5,-3782.51) ""(1424.83,-3794.72) ""(1424.83,-3794.72) ""(1424.83,-3794.72) ""(1424.83,-3794.71) ""(1424.83,-3794.71) ""(1424.96,-3783.12) ""(1424.96,-3783.12) ""(1424.96,-3783.12) ""(1424.96,-3783.12) ""(1425,-3797.36) ""(1425,-3797.36) ""(1425,-3797.36) ""(1425,-3797.36) ""(1425,-3797.36) ""(1425.43,-3783.92) ""(1425.43,-3783.92) ""(1425.43,-3783.92) ""(1425.43,-3783.92) ""(1425.83,-3784.79) ""(1425.83,-3784.79) ""(1425.83,-3784.79) ""(1425.83,-3784.79) ""(1426.1,-3785.86) ""(1426.1,-3785.86) ""(1426.1,-3785.86) ""(1426.1,-3785.86) ""(1426.3,-3786.59) ""(1426.3,-3786.59) ""(1426.3,-3786.59) ""(1426.3,-3786.59) ""(1426.37,-3794.37) ""(1426.37,-3794.37) ""(1426.37,-3794.37) ""(1426.37,-3794.37) ""(1426.37,-3794.37) ""(1426.64,-3787.66) ""(1426.64,-3787.66) ""(1426.64,-3787.66) ""(1426.64,-3787.66) ""(1426.75,-3787.97) ""(1426.75,-3787.97) ""(1426.75,-3787.97) ""(1426.75,-3787.97) ""(1426.75,-3787.97) ""(1427.17,-3783.39) ""(1427.17,-3783.39) ""(1427.17,-3777.8) ""(1427.17,-3783.39) ""(1427.17,-3783.39) ""(1427.17,-3777.8) ""(1427.17,-3777.8) ""(1427.17,-3777.8) ""(1427.17,-3777.8) ""(1427.94,-3777.03) ""(1427.94,-3777.03) ""(1427.94,-3777.03) ""(1427.94,-3777.03) ""(1427.94,-3777.03) ""(1433.2,-3780.51) ""(1433.2,-3780.51) ""(1433.4,-3780.17) ""(1433.4,-3780.17) ""(1433.4,-3780.17) ""(1433.4,-3780.17) ""(1433.6,-3794.42) ""(1433.6,-3794.42) ""(1433.6,-3794.42) ""(1433.6,-3794.42) ""(1433.6,-3794.42) ""(1434.13,-3779.77) ""(1434.13,-3779.77) ""(1434.13,-3779.77) ""(1434.13,-3779.77) ""(1434.76,-3777.03) ""(1434.76,-3777.03) ""(1434.76,-3777.03) ""(1434.76,-3777.03) ""(1434.76,-3777.03) ""(1434.77,-3797.36) ""(1434.77,-3797.36) ""(1434.77,-3797.36) ""(1434.77,-3797.36) ""(1434.77,-3797.36) ""(1434.83,-3779.71) ""(1434.83,-3779.71) ""(1434.83,-3779.71) ""(1434.83,-3779.71) ""(1434.83,-3779.71) ""(1434.94,-3794.72) ""(1434.94,-3794.71) ""(1434.94,-3794.71) ""(1434.94,-3794.71) ""(1434.94,-3794.72) ""(1435.53,-3778.95) ""(1435.53,-3778.95) ""(1435.53,-3778.95) ""(1435.53,-3778.95) ""(1435.53,-3778.95) ""(1435.53,-3777.8) ""(1435.53,-3777.8) ""(1435.53,-3777.8) ""(1435.53,-3777.8) ""(1435.53,-3777.8) ""(1435.54,-3796.59) ""(1435.54,-3796.59) ""(1435.54,-3796.59) ""(1435.54,-3796.59) ""(1435.54,-3796.59) ""(1435.54,-3795.47) ""(1435.54,-3795.47) ""(1435.54,-3795.47) ""(1435.54,-3795.47) ""(1435.54,-3795.47) ""(1439.28,-3793.38) ""(1439.28,-3793.38) ""(1439.32,-3794.59) ""(1439.32,-3794.59) ""(1439.32,-3794.59) ""(1439.32,-3794.59) ""(1439.32,-3794.59) ""(1439.41,-3786.56) ""(1439.41,-3786.56) ""(1439.41,-3786.56) ""(1439.41,-3786.56) ""(1439.41,-3786.56) ""(1439.41,-3785.3) ""(1439.41,-3785.3) ""(1439.41,-3785.3) ""(1439.41,-3785.3) ""(1439.55,-3784.51) ""(1439.55,-3784.51) ""(1439.55,-3784.51) ""(1439.55,-3784.51) ""(1439.8,-3783.73) ""(1439.8,-3783.73) ""(1439.8,-3783.73) ""(1439.8,-3783.73) ""(1439.82,-3794.96) ""(1439.82,-3794.96) ""(1439.82,-3794.96) ""(1439.82,-3794.96) ""(1440.09,-3782.72) ""(1440.09,-3782.72) ""(1440.09,-3782.72) ""(1440.09,-3782.72) ""(1440.18,-3787.33) ""(1440.18,-3787.33) ""(1440.23,-3792.53) ""(1440.23,-3792.53) ""(1440.76,-3780.98) ""(1440.76,-3780.98) ""(1440.76,-3780.98) ""(1440.76,-3780.98) ""(1441.23,-3795.96) ""(1441.23,-3795.96) ""(1441.23,-3795.96) ""(1441.23,-3795.96) ""(1441.31,-3792.57) ""(1441.31,-3792.57) ""(1441.31,-3792.57) ""(1441.31,-3792.57) ""(1441.31,-3792.57) ""(1441.76,-3779.51) ""(1441.76,-3779.51) ""(1441.76,-3779.51) ""(1441.76,-3779.51) ""(1442.3,-3793.62) ""(1442.3,-3793.62) ""(1442.3,-3793.62) ""(1442.3,-3793.62) ""(1442.56,-3796.7) ""(1442.56,-3796.7) ""(1442.56,-3796.7) ""(1442.56,-3796.7) ""(1443.37,-3778.11) ""(1443.37,-3778.11) ""(1443.37,-3778.11) ""(1443.37,-3778.11) ""(1443.5,-3794.49) ""(1443.5,-3794.49) ""(1443.5,-3794.49) ""(1443.5,-3794.49) ""(1444.04,-3797.3) ""(1444.04,-3797.3) ""(1444.04,-3797.3) ""(1444.04,-3797.3) ""(1444.51,-3794.89) ""(1444.51,-3794.89) ""(1444.51,-3794.89) ""(1444.51,-3794.89) ""(1444.57,-3777.3) ""(1444.57,-3777.3) ""(1444.57,-3777.3) ""(1444.57,-3777.3) ""(1445.37,-3797.63) ""(1445.37,-3797.63) ""(1445.38,-3797.63) ""(1445.38,-3797.63) ""(1445.58,-3794.96) ""(1445.58,-3794.96) ""(1445.58,-3784.29) ""(1445.58,-3782.72) ""(1445.58,-3782.72) ""(1445.58,-3794.96) ""(1445.58,-3794.96) ""(1445.58,-3784.29) ""(1445.58,-3784.29) ""(1445.58,-3784.29) ""(1445.58,-3784.29) ""(1445.58,-3782.72) ""(1445.58,-3782.72) ""(1445.91,-3781.38) ""(1445.91,-3781.38) ""(1445.91,-3781.38) ""(1445.91,-3781.38) ""(1446.18,-3776.77) ""(1446.18,-3776.77) ""(1446.18,-3776.77) ""(1446.18,-3776.77) ""(1446.31,-3780.51) ""(1446.31,-3780.51) ""(1446.31,-3780.51) ""(1446.31,-3780.51) ""(1446.35,-3785.06) ""(1446.35,-3785.06) ""(1446.35,-3785.06) ""(1446.35,-3785.06) ""(1446.35,-3785.06) ""(1446.98,-3779.98) ""(1446.98,-3779.98) ""(1446.98,-3779.98) ""(1446.98,-3779.98) ""(1447.65,-3794.89) ""(1447.65,-3794.89) ""(1447.65,-3779.64) ""(1447.65,-3779.64) ""(1447.65,-3794.89) ""(1447.65,-3794.89) ""(1447.65,-3779.64) ""(1447.65,-3779.64) ""(1447.72,-3797.7) ""(1447.72,-3797.7) ""(1447.72,-3797.7) ""(1447.72,-3797.7) ""(1448.12,-3776.63) ""(1448.12,-3776.63) ""(1448.12,-3776.63) ""(1448.12,-3776.63) ""(1448.39,-3779.58) ""(1448.39,-3779.58) ""(1448.39,-3779.58) ""(1448.39,-3779.58) ""(1449.06,-3794.29) ""(1449.06,-3794.29) ""(1449.06,-3794.29) ""(1449.06,-3794.29) ""(1449.32,-3779.64) ""(1449.32,-3779.64) ""(1449.32,-3779.64) ""(1449.32,-3779.64) ""(1449.59,-3797.7) ""(1449.59,-3797.7) ""(1449.59,-3797.7) ""(1449.59,-3797.7) ""(1449.73,-3779.84) ""(1449.73,-3779.84) ""(1449.73,-3779.84) ""(1449.73,-3779.84) ""(1450.19,-3776.7) ""(1450.19,-3776.7) ""(1450.19,-3776.7) ""(1450.19,-3776.7) ""(1450.4,-3780.18) ""(1450.4,-3780.18) ""(1450.4,-3780.18) ""(1450.4,-3780.18) ""(1450.8,-3797.57) ""(1450.8,-3797.57) ""(1450.8,-3797.57) ""(1450.8,-3797.57) ""(1451,-3780.71) ""(1451,-3780.71) ""(1451,-3780.71) ""(1451,-3780.71) ""(1451.29,-3785.06) ""(1451.29,-3785.06) ""(1451.29,-3785.06) ""(1451.29,-3785.06) ""(1451.29,-3785.06) ""(1451.33,-3781.25) ""(1451.33,-3781.25) ""(1451.33,-3781.25) ""(1451.33,-3781.25) ""(1451.37,-3787.33) ""(1451.37,-3787.33) ""(1451.37,-3787.33) ""(1451.37,-3787.33) ""(1451.37,-3787.33) ""(1451.53,-3781.77) ""(1451.53,-3781.77) ""(1451.53,-3781.77) ""(1451.53,-3781.77) ""(1451.67,-3791.21) ""(1451.67,-3791.21) ""(1451.67,-3791.21) ""(1451.67,-3791.21) ""(1451.72,-3782.31) ""(1451.72,-3782.31) ""(1451.72,-3782.31) ""(1451.72,-3782.31) ""(1451.89,-3782.89) ""(1451.89,-3782.89) ""(1451.89,-3782.89) ""(1451.89,-3782.89) ""(1451.93,-3777.17) ""(1451.93,-3777.17) ""(1451.93,-3777.17) ""(1451.93,-3777.17) ""(1452,-3790.14) ""(1452,-3790.14) ""(1452,-3790.14) ""(1452,-3790.14) ""(1452.07,-3784.29) ""(1452.07,-3784.29) ""(1452.07,-3784.29) ""(1452.07,-3784.29) ""(1452.07,-3784.29) ""(1452.07,-3783.7) ""(1452.07,-3783.7) ""(1452.07,-3783.7) ""(1452.07,-3783.7) ""(1452.14,-3788.94) ""(1452.14,-3788.94) ""(1452.14,-3788.1) ""(1452.14,-3788.1) ""(1452.14,-3788.94) ""(1452.14,-3788.94) ""(1452.14,-3788.1) ""(1452.14,-3788.1) ""(1452.14,-3788.1) ""(1452.27,-3797.16) ""(1452.27,-3797.16) ""(1452.27,-3797.16) ""(1452.27,-3797.16) ""(1453.34,-3777.64) ""(1453.34,-3777.64) ""(1453.34,-3777.64) ""(1453.34,-3777.64) ""(1453.88,-3796.09) ""(1453.88,-3796.09) ""(1453.88,-3796.09) ""(1453.88,-3796.09) ""(1454.28,-3778.24) ""(1454.28,-3778.24) ""(1454.28,-3778.24) ""(1454.28,-3778.24) ""(1455.01,-3795.16) ""(1455.01,-3795.16) ""(1455.01,-3795.16) ""(1455.01,-3795.16) ""(1455.28,-3779.11) ""(1455.28,-3779.11) ""(1455.28,-3779.11) ""(1455.28,-3779.11) ""(1456.02,-3794.22) ""(1456.02,-3794.22) ""(1456.02,-3794.22) ""(1456.02,-3794.22) ""(1456.15,-3780.18) ""(1456.15,-3780.18) ""(1456.15,-3780.18) ""(1456.15,-3780.18) ""(1457.02,-3792.95) ""(1457.02,-3792.95) ""(1457.02,-3792.95) ""(1457.02,-3792.95) ""(1457.22,-3781.78) ""(1457.22,-3781.78) ""(1457.22,-3781.78) ""(1457.22,-3781.78) ""(1457.82,-3791.28) ""(1457.82,-3791.28) ""(1457.82,-3791.28) ""(1457.82,-3791.28) ""(1458.03,-3783.25) ""(1458.03,-3783.25) ""(1458.03,-3783.25) ""(1458.03,-3783.25) ""(1458.29,-3789.94) ""(1458.29,-3789.94) ""(1458.29,-3789.94) ""(1458.29,-3789.94) ""(1458.43,-3784.32) ""(1458.43,-3784.32) ""(1458.43,-3784.32) ""(1458.43,-3784.32) ""(1458.56,-3788.4) ""(1458.56,-3788.4) ""(1458.56,-3785.66) ""(1458.56,-3785.66) ""(1458.56,-3788.4) ""(1458.56,-3788.4) ""(1458.56,-3785.66) ""(1458.56,-3785.66) ""(1458.63,-3787) ""(1458.63,-3787) ""(1458.63,-3787) ""(1458.63,-3787) ""(1462.46,-3789.72) ""(1462.46,-3789.72) ""(1462.46,-3786.89) ""(1462.46,-3786.89) ""(1462.46,-3789.72) ""(1462.46,-3789.72) ""(1462.46,-3786.89) ""(1462.46,-3786.89) ""(1462.92,-3791.36) ""(1462.92,-3791.36) ""(1462.92,-3791.36) ""(1462.92,-3791.36) ""(1463.38,-3784.34) ""(1463.38,-3784.34) ""(1463.38,-3784.34) ""(1463.38,-3784.34) ""(1463.92,-3793.18) ""(1463.92,-3793.18) ""(1463.92,-3793.18) ""(1463.92,-3793.18) ""(1464.47,-3782.89) ""(1464.47,-3782.89) ""(1464.47,-3782.89) ""(1464.47,-3782.89) ""(1464.84,-3775.53) ""(1464.84,-3775.53) ""(1464.84,-3775.53) ""(1464.84,-3775.53) ""(1464.84,-3775.53) ""(1464.84,-3769.71) ""(1464.84,-3769.71) ""(1464.84,-3769.71) ""(1464.84,-3769.71) ""(1464.84,-3769.71) ""(1465.29,-3795) ""(1465.29,-3795) ""(1465.29,-3795) ""(1465.29,-3795) ""(1465.61,-3776.3) ""(1465.61,-3776.3) ""(1465.61,-3768.94) ""(1465.61,-3768.94) ""(1465.62,-3776.3) ""(1465.62,-3776.3) ""(1465.62,-3776.3) ""(1465.62,-3768.94) ""(1465.62,-3768.94) ""(1465.62,-3768.94) ""(1465.76,-3768.94) ""(1465.76,-3768.94) ""(1465.76,-3768.94) ""(1465.76,-3768.94) ""(1466.25,-3769.04) ""(1466.25,-3769.04) ""(1466.25,-3769.04) ""(1466.25,-3769.04) ""(1466.63,-3769.25) ""(1466.63,-3769.25) ""(1466.63,-3769.25) ""(1466.63,-3769.25) ""(1466.91,-3769.5) ""(1466.91,-3769.5) ""(1466.91,-3769.5) ""(1466.91,-3769.5) ""(1467.03,-3769.64) ""(1467.03,-3769.64) ""(1467.03,-3769.64) ""(1467.03,-3769.64) ""(1467.03,-3769.64) ""(1467.1,-3776.3) ""(1467.1,-3776.3) ""(1467.11,-3776.3) ""(1467.11,-3776.3) ""(1467.11,-3776.3) ""(1467.75,-3796.91) ""(1467.75,-3796.91) ""(1467.75,-3796.91) ""(1467.75,-3796.91) ""(1467.87,-3775.59) ""(1467.87,-3775.59) ""(1467.87,-3775.59) ""(1467.87,-3775.59) ""(1467.87,-3775.59) ""(1467.93,-3774.87) ""(1467.93,-3774.87) ""(1467.93,-3774.87) ""(1467.93,-3774.87) ""(1467.98,-3769.83) ""(1467.98,-3769.83) ""(1467.98,-3769.83) ""(1467.98,-3769.83) ""(1467.98,-3769.83) ""(1468.21,-3773.96) ""(1468.21,-3773.96) ""(1468.21,-3773.96) ""(1468.21,-3773.96) ""(1468.57,-3790.63) ""(1468.57,-3790.63) ""(1468.57,-3790.63) ""(1468.57,-3790.63) ""(1468.66,-3791.72) ""(1468.66,-3791.72) ""(1468.66,-3791.72) ""(1468.66,-3791.72) ""(1468.66,-3773.05) ""(1468.66,-3773.05) ""(1468.66,-3773.05) ""(1468.66,-3773.05) ""(1468.75,-3793.09) ""(1468.75,-3793.09) ""(1468.75,-3793.09) ""(1468.75,-3793.09) ""(1468.75,-3789.63) ""(1468.75,-3789.63) ""(1468.75,-3789.63) ""(1468.75,-3789.63) ""(1468.75,-3780.15) ""(1468.75,-3780.15) ""(1468.75,-3780.15) ""(1468.75,-3780.15) ""(1468.92,-3769.32) ""(1468.92,-3769.32) ""(1468.92,-3769.32) ""(1468.92,-3769.32) ""(1469.39,-3771.96) ""(1469.39,-3771.96) ""(1469.39,-3771.96) ""(1469.39,-3771.96) ""(1469.48,-3788.44) ""(1469.48,-3788.44) ""(1469.48,-3788.44)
